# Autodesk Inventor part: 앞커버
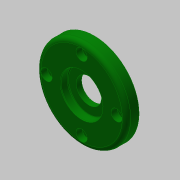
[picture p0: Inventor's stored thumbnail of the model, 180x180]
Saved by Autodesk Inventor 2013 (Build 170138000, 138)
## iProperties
Created: 2020-07
Part Number: 앞커버
Material: 알루미늄 6061
Document SubType Name: Modeling
Designer: mduedu
Density: 1 g/cm^3
Author: mduedu
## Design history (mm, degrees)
sketch "스케치1"
  geometry: L1 (0, 0)-(9, 0); L2 (9, 0)-(9, 32); L3 (9, 32)-(0, 32); L4 (0, 32)-(0, 0); L5 (9, 0)-(12, 0); L6 (12, 0)-(12, 20); L7 (12, 20)-(9, 20); L8 (9, 20)-(9, 0)
  constraints: 16 end point, 4 parallel, 2 horizontal, 2 perpendicular
  dimensions: "d0" = 64 diameter of L3 L1; "d2" = 40 diameter of L7 L5; "d3" = 12 distance between parallel lines of L6 L4; "d4" = 3 distance between parallel lines of L2 L6
revolve "회전1" sketch "스케치1" stored, may be unused: angle "d5" = 90 deg
sketch "스케치2"
  geometry: L1 (0, -32)-(0, 32) reference; L2 (0, 32)-(9, 32) reference; L3 (9, 32)-(9, 20) reference; L4 (9, 20)-(12, 20) reference; L5 (12, 20)-(12, -20) reference; L6 (12, -20)-(9, -20) reference; L7 (9, -20)-(9, -32) reference; L8 (9, -32)-(0, -32) reference; L9 (0, 0)-(5.2, 0); L10 (5.2, 0)-(5.2, 15); L11 (5.2, 15)-(0, 15); L12 (0, 15)-(0, 0); L13 (5.2, 0)-(9, 0); L14 (9, 0)-(9, 9); L15 (9, 9)-(5.2, 9); L16 (5.2, 9)-(5.2, 0); L17 (9, 0)-(12, 0); L18 (12, 0)-(12, 15); L19 (12, 15)-(9, 15); L20 (9, 15)-(9, 0)
  constraints: 24 end point, 6 parallel, 3 horizontal, 3 perpendicular, 1 point on line
  dimensions: "d6" = 30 diameter of L11 L9; "d8" = 18 diameter of L15 L13; "d9" = 30 diameter of L19 L17; "d10" = 3 distance of L18.end L19.end; "d11" = 5.2 distance of L10.end L11.end
revolve "회전2" sketch "스케치2" stored, may be unused: angle "d12" = 90 deg
fillet "모깎기1" dims "d13" = 3
fillet "모깎기2" dims "d14" = 3
chamfer "모따기1" distance "d15" = 1; stored, may be unused: second distance "d16" = 2, angle "d17" = 45 deg
sketch "스케치3" dims "d18" = 50
  geometry: 3 further points
  constraints: 2 vertical alignment, 1 coincident, 2 other
hole "구멍1" sketch "스케치3" at (0, 25) diameter "d19" = 4.5; stored, may be unused: countersink angle "d23" = 90 deg, drill point angle "d25" = 118 deg; dims "d20" = 6, "d21" = 8, "d22" = 4.4, "d24" = 8
fillet "모깎기3" dims "d29" = 0.5
chamfer "모따기2" distance "d30" = 0.5; stored, may be unused: second distance "d31" = 2, angle "d32" = 30 deg
node "솔리드1"
pattern_circular "원형 패턴1" dims angle "d27" = 360 deg
node "절단 모서리 투영1"
